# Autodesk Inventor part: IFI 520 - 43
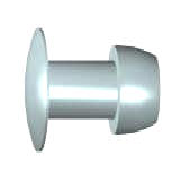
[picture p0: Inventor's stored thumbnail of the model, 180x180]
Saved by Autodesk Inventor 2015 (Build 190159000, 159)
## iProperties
Created: 2013-02
Part Number: IFI 520 - 43
Material: Steel, Mild
Description: Protruding Head Style Break Mandrel Closed End Blind Rivet - Metric
Document SubType Name: Modeling
Standard: IFI 520
Designer: Dave
Standard Revision: 2003
Standards Organization: ANSI
Language: en-US
Size Designation: 43
Categories: <MemberInstance><Categories><Category DisplayName="Fasteners" InternalName="e4da775c-781d-43d5-af7c-5136215cf5a6" Mnemonic="FSTN"><Category DisplayName="Rivets"
Density: 1 g/cm^3
Appearance: Steel
IsCustomPart: 1
Author: Dave
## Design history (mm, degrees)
sketch "Sketch1"
  geometry: L1 (-0.254, 3.2)-(0, 3.2); L2 (0, 3.2)-(0, 1.6); L3 (0, 1.6)-(3.301, 1.6); L4 (3.301, 1.6)-(3.301, 2.304); L5 (-1.27, 0)-(7.111, 0); L6 (7.111, 0)-(7.111, 1.76); L7 (-2.918, 0)-(6.759, 0) reference; L8 (0, -5.472)-(0, 4.751) reference; A1 r 5.547 centre (4.277, 0) between (-0.254, 3.2) and (-1.27, 0); A2 r 6.4 centre (4.343, -4.011) between (7.111, 1.76) and (3.301, 2.304)
  constraints: 12 end point, 4 point on circle, 3 perpendicular, 2 centre point, 2 collinear, 2 parallel, 1 horizontal, 1 point on line
  dimensions: "d0" = 6.4 diameter of L1 L5 (= KOD); "d1" = 3.2 diameter of L3 L5 (= NND); "d2" = 4.608 diameter of L4.end L5 (= 0.72 x KOD); "d3" = 3.52 diameter of L6.end L5 (= 0.55 x KOD); "d4" = 6.4 radius of A2 (= KOD); "d5" = 3.81 distance between parallel lines of L6 L4 (= 3 x KOH); "d6" = 3.301 distance of L2.end L3.end (computed from KLG); "d7" = 0.254 distance of L1.start L1.end (= PHH); "d8" = 1.27 distance from line of L5.start L2 (= KOH)
revolve "Body" sketch "Sketch1" stored, may be unused: angle "d9" = 90 deg
body "Solid1"
fillet "Fillet1" dims "d10" = 0.7 (= R1)
other parameters: "NND" = 3.2 [user parameter; used in 1 equation term], "KLG" = 3.3 [user parameter; used in 1 equation term], "KOH" = 1.27 [user parameter; used in 2 equation terms], "KOD" = 6.4 [user parameter; used in 4 equation terms], "PHH" = 0.254 [user parameter; used in 1 equation term], "R1" = 0.7 [user parameter; used in 1 equation term], "d11" = 0, "d12" = 0, "d13" = 0, "BOR" = 1.85 [user parameter], "KLGMAX" = 4.8 [user parameter], "KLGMIN" = 3.3 [user parameter]
